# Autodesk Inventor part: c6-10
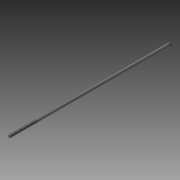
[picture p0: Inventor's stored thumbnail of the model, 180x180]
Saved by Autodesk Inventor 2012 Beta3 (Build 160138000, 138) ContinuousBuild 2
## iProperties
Created: 2010-12
Part Number: c6-10
Material: Steel, High Strength Low Alloy
Document SubType Name: Modeling
Designer: Beta-8540w
Mass: 1418.96 g
Surface Area: 459.995 cm^2
Volume: 180.99 cm^3
Density: 7.84 g/cm^3
Author: Beta-8540w
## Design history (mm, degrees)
sketch "Sketch1"
  geometry: C1 r 7.938 at (40.536, 0); 1 further point
  constraints: 1 centre point
  dimensions: "d0" = 15.875 diameter of C1
extrude "Extrusion1" new body sketch "Sketch1" distance "d1" = 914.4; taper "d2" = 0 deg
thread "Thread1" dims "d3" = 12.7, "d4" = 0
thread "Thread2" dims "d5" = 152.4, "d6" = 0
chamfer "Chamfer1" distance "d7" = 1.524; stored, may be unused: second distance "d8" = 3.175, angle "d9" = 45 deg
body "Solid1"
